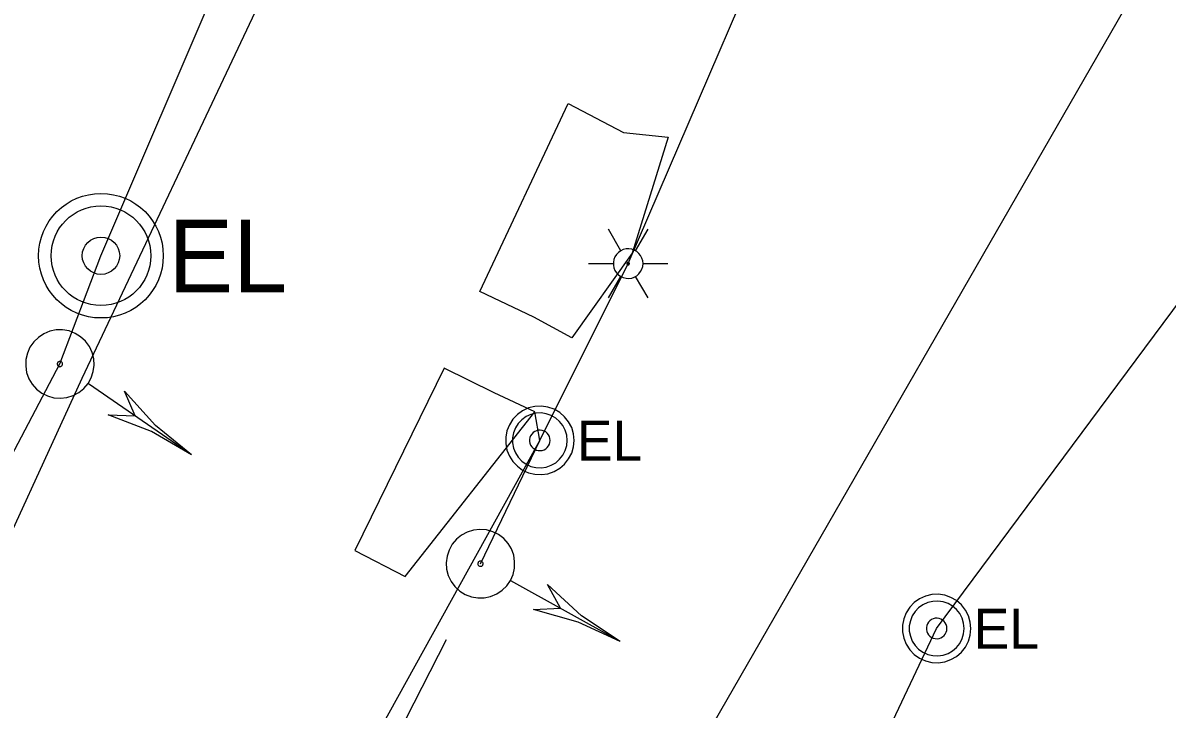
# Model space of a CAD drawing. Extents: x 596028 to 606371, y 330010 to 403088.
# Drawn here: x 604782.6 to 604892.8, y 331025.8 to 331091.9 of the extents above; entities that cross this region are included whole.
import ezdxf

# ---------------------------------------------------------------- set-up
doc = ezdxf.new("R2010")
doc.units = 0
for name, color, linetype in [('E_LTG', 7, 'Continuous'), ('E_SIG', 7, 'Continuous'), ('E_UTL_E', 7, 'Continuous'), ('E_UTL_E_UG', 7, 'Continuous'), ('E_UTL_G_UG', 7, 'Continuous'), ('E_UTL_Loop_UG', 7, 'Continuous'), ('E_UTL_W_UG', 7, 'Continuous')]:
    doc.layers.add(name, color=color, linetype=linetype)

msp = doc.modelspace()

# ---------------------------------------------------------------- linework, layer by layer
at = {"layer": 'E_LTG'}
for points in [[(604840.16, 331069.93), (604838.97, 331071.99)], [(604841.58, 331069.93), (604842.78, 331071.99)], [(604842.3, 331068.69), (604842.27, 331068.96), (604842.2, 331069.22), (604842.07, 331069.46), (604841.9, 331069.67), (604841.7, 331069.85), (604841.46, 331069.99), (604841.21, 331070.08), (604840.94, 331070.12), (604840.67, 331070.1), (604840.4, 331070.04), (604840.16, 331069.93), (604839.93, 331069.77), (604839.75, 331069.57), (604839.6, 331069.34), (604839.5, 331069.09), (604839.45, 331068.82), (604839.45, 331068.55), (604839.5, 331068.29), (604839.6, 331068.03), (604839.75, 331067.8), (604839.93, 331067.61), (604840.16, 331067.45), (604840.4, 331067.34), (604840.67, 331067.27), (604840.94, 331067.26), (604841.21, 331067.3), (604841.46, 331067.39), (604841.7, 331067.52), (604841.9, 331067.7), (604842.07, 331067.92), (604842.2, 331068.16), (604842.27, 331068.42), (604842.3, 331068.69)], [(604842.3, 331068.69), (604842.27, 331068.96), (604842.2, 331069.22), (604842.07, 331069.46), (604841.9, 331069.67), (604841.7, 331069.85), (604841.46, 331069.99), (604841.21, 331070.08), (604840.94, 331070.12), (604840.67, 331070.1), (604840.4, 331070.04), (604840.16, 331069.93), (604839.93, 331069.77), (604839.75, 331069.57), (604839.6, 331069.34), (604839.5, 331069.09), (604839.45, 331068.82), (604839.45, 331068.55), (604839.5, 331068.29), (604839.6, 331068.03), (604839.75, 331067.8), (604839.93, 331067.61), (604840.16, 331067.45), (604840.4, 331067.34), (604840.67, 331067.27), (604840.94, 331067.26), (604841.21, 331067.3), (604841.46, 331067.39), (604841.7, 331067.52), (604841.9, 331067.7), (604842.07, 331067.92), (604842.2, 331068.16), (604842.27, 331068.42), (604842.3, 331068.69)], [(604842.3, 331068.69), (604842.27, 331068.96), (604842.2, 331069.22), (604842.07, 331069.46), (604841.9, 331069.67), (604841.7, 331069.85), (604841.46, 331069.99), (604841.21, 331070.08), (604840.94, 331070.12), (604840.67, 331070.1), (604840.4, 331070.04), (604840.16, 331069.93), (604839.93, 331069.77), (604839.75, 331069.57), (604839.6, 331069.34), (604839.5, 331069.09), (604839.45, 331068.82), (604839.45, 331068.55), (604839.5, 331068.29), (604839.6, 331068.03), (604839.75, 331067.8), (604839.93, 331067.61), (604840.16, 331067.45), (604840.4, 331067.34), (604840.67, 331067.27), (604840.94, 331067.26), (604841.21, 331067.3), (604841.46, 331067.39), (604841.7, 331067.52), (604841.9, 331067.7), (604842.07, 331067.92), (604842.2, 331068.16), (604842.27, 331068.42), (604842.3, 331068.69)], [(604840.99, 331068.69), (604840.99, 331068.71), (604840.98, 331068.73), (604840.97, 331068.75), (604840.96, 331068.77), (604840.94, 331068.78), (604840.92, 331068.8), (604840.9, 331068.8), (604840.88, 331068.81), (604840.85, 331068.81), (604840.83, 331068.8), (604840.81, 331068.79), (604840.79, 331068.78), (604840.78, 331068.76), (604840.76, 331068.74), (604840.76, 331068.72), (604840.75, 331068.7), (604840.75, 331068.68), (604840.76, 331068.65), (604840.76, 331068.63), (604840.78, 331068.61), (604840.79, 331068.6), (604840.81, 331068.58), (604840.83, 331068.58), (604840.85, 331068.57), (604840.88, 331068.57), (604840.9, 331068.57), (604840.92, 331068.58), (604840.94, 331068.59), (604840.96, 331068.61), (604840.97, 331068.62), (604840.98, 331068.64), (604840.99, 331068.67), (604840.99, 331068.69)], [(604837.06, 331068.69), (604839.44, 331068.69)], [(604842.3, 331068.69), (604844.68, 331068.69)], [(604838.97, 331065.39), (604840.16, 331067.45)], [(604842.78, 331065.39), (604841.58, 331067.45)]]:
    msp.add_lwpolyline(points, dxfattribs=at)
at = {"layer": 'E_SIG'}
for points in [[(604788.87, 331057.14), (604789.17, 331057.69), (604789.37, 331058.28), (604789.45, 331058.91), (604789.41, 331059.53), (604789.25, 331060.14), (604788.99, 331060.71), (604788.61, 331061.21), (604788.15, 331061.64), (604787.62, 331061.97), (604787.04, 331062.2), (604786.42, 331062.31), (604785.79, 331062.3), (604785.18, 331062.17), (604784.6, 331061.93), (604784.08, 331061.58), (604783.63, 331061.14), (604783.27, 331060.63), (604783.02, 331060.05), (604782.88, 331059.44), (604782.86, 331058.81), (604782.95, 331058.19), (604783.17, 331057.6), (604783.49, 331057.07), (604783.91, 331056.6), (604784.41, 331056.22), (604784.97, 331055.94), (604785.57, 331055.77), (604786.2, 331055.72), (604786.82, 331055.79), (604787.42, 331055.97), (604787.97, 331056.27), (604788.46, 331056.66), (604788.87, 331057.14)], [(604786.36, 331058.87), (604786.38, 331058.92), (604786.4, 331058.96), (604786.4, 331059.01), (604786.4, 331059.06), (604786.39, 331059.1), (604786.37, 331059.15), (604786.34, 331059.18), (604786.3, 331059.22), (604786.26, 331059.24), (604786.22, 331059.26), (604786.17, 331059.27), (604786.12, 331059.27), (604786.08, 331059.26), (604786.03, 331059.24), (604785.99, 331059.21), (604785.96, 331059.18), (604785.93, 331059.14), (604785.91, 331059.1), (604785.9, 331059.05), (604785.9, 331059), (604785.91, 331058.95), (604785.92, 331058.91), (604785.95, 331058.87), (604785.98, 331058.83), (604786.02, 331058.8), (604786.06, 331058.78), (604786.11, 331058.77), (604786.15, 331058.76), (604786.2, 331058.77), (604786.25, 331058.78), (604786.29, 331058.81), (604786.33, 331058.84), (604786.36, 331058.87)], [(604798.82, 331050.26), (604788.91, 331057.11)], [(604793.39, 331054.01), (604792.36, 331056.4)], [(604798.82, 331050.26), (604795.35, 331053.08), (604792.36, 331056.39)], [(604798.82, 331050.26), (604794.96, 331052.51), (604790.8, 331054.13)], [(604790.8, 331054.13), (604793.39, 331054.01)], [(604829.53, 331038.17), (604829.79, 331038.75), (604829.92, 331039.36), (604829.94, 331039.99), (604829.85, 331040.61), (604829.63, 331041.2), (604829.31, 331041.73), (604828.89, 331042.2), (604828.39, 331042.58), (604827.83, 331042.86), (604827.22, 331043.03), (604826.6, 331043.08), (604825.97, 331043.01), (604825.38, 331042.82), (604824.82, 331042.52), (604824.34, 331042.13), (604823.93, 331041.65), (604823.63, 331041.1), (604823.43, 331040.5), (604823.35, 331039.88), (604823.39, 331039.26), (604823.55, 331038.65), (604823.82, 331038.08), (604824.19, 331037.58), (604824.65, 331037.15), (604825.19, 331036.82), (604825.77, 331036.6), (604826.39, 331036.49), (604827.02, 331036.5), (604827.63, 331036.63), (604828.21, 331036.87), (604828.73, 331037.22), (604829.18, 331037.66), (604829.53, 331038.17)], [(604826.87, 331039.65), (604826.89, 331039.7), (604826.9, 331039.75), (604826.9, 331039.79), (604826.9, 331039.84), (604826.88, 331039.89), (604826.85, 331039.93), (604826.82, 331039.96), (604826.78, 331039.99), (604826.74, 331040.01), (604826.69, 331040.03), (604826.65, 331040.03), (604826.6, 331040.02), (604826.55, 331040.01), (604826.51, 331039.99), (604826.47, 331039.96), (604826.44, 331039.92), (604826.42, 331039.88), (604826.4, 331039.83), (604826.4, 331039.79), (604826.4, 331039.74), (604826.41, 331039.69), (604826.43, 331039.65), (604826.46, 331039.61), (604826.5, 331039.58), (604826.54, 331039.55), (604826.58, 331039.53), (604826.63, 331039.53), (604826.68, 331039.53), (604826.73, 331039.54), (604826.77, 331039.55), (604826.81, 331039.58), (604826.84, 331039.61), (604826.87, 331039.65)], [(604840.11, 331032.29), (604829.58, 331038.14)], [(604840.11, 331032.29), (604836.38, 331034.76), (604833.09, 331037.77)], [(604834.34, 331035.5), (604833.09, 331037.77)], [(604831.75, 331035.37), (604834.34, 331035.5)], [(604840.11, 331032.29), (604836.05, 331034.15), (604831.75, 331035.37)]]:
    msp.add_lwpolyline(points, dxfattribs=at)
at = {"layer": 'E_UTL_E'}
for points in [[(604835.66, 331051.66), (604835.6, 331052.28), (604835.43, 331052.89), (604835.14, 331053.44), (604834.75, 331053.94), (604834.28, 331054.35), (604833.73, 331054.66), (604833.14, 331054.87), (604832.52, 331054.96), (604831.89, 331054.93), (604831.28, 331054.78), (604830.71, 331054.52), (604830.2, 331054.15), (604829.77, 331053.7), (604829.43, 331053.17), (604829.2, 331052.59), (604829.08, 331051.97), (604829.08, 331051.35), (604829.2, 331050.73), (604829.43, 331050.15), (604829.77, 331049.62), (604830.2, 331049.17), (604830.71, 331048.8), (604831.28, 331048.54), (604831.89, 331048.39), (604832.52, 331048.36), (604833.14, 331048.45), (604833.73, 331048.66), (604834.28, 331048.97), (604834.75, 331049.38), (604835.14, 331049.87), (604835.43, 331050.43), (604835.6, 331051.03), (604835.66, 331051.66)], [(604835.66, 331051.66), (604835.6, 331052.28), (604835.43, 331052.89), (604835.14, 331053.44), (604834.75, 331053.94), (604834.28, 331054.35), (604833.73, 331054.66), (604833.14, 331054.87), (604832.52, 331054.96), (604831.89, 331054.93), (604831.28, 331054.78), (604830.71, 331054.52), (604830.2, 331054.15), (604829.77, 331053.7), (604829.43, 331053.17), (604829.2, 331052.59), (604829.08, 331051.97), (604829.08, 331051.35), (604829.2, 331050.73), (604829.43, 331050.15), (604829.77, 331049.62), (604830.2, 331049.17), (604830.71, 331048.8), (604831.28, 331048.54), (604831.89, 331048.39), (604832.52, 331048.36), (604833.14, 331048.45), (604833.73, 331048.66), (604834.28, 331048.97), (604834.75, 331049.38), (604835.14, 331049.87), (604835.43, 331050.43), (604835.6, 331051.03), (604835.66, 331051.66)], [(604835, 331051.66), (604834.95, 331052.16), (604834.81, 331052.64), (604834.58, 331053.09), (604834.27, 331053.48), (604833.89, 331053.81), (604833.46, 331054.06), (604832.98, 331054.22), (604832.49, 331054.3), (604831.99, 331054.27), (604831.5, 331054.15), (604831.04, 331053.95), (604830.63, 331053.65), (604830.29, 331053.29), (604830.02, 331052.87), (604829.83, 331052.4), (604829.73, 331051.91), (604829.73, 331051.41), (604829.83, 331050.92), (604830.02, 331050.45), (604830.29, 331050.03), (604830.63, 331049.66), (604831.04, 331049.37), (604831.5, 331049.16), (604831.99, 331049.05), (604832.49, 331049.02), (604832.98, 331049.09), (604833.46, 331049.26), (604833.89, 331049.51), (604834.27, 331049.84), (604834.58, 331050.23), (604834.81, 331050.68), (604834.95, 331051.16), (604835, 331051.66)], [(604835, 331051.66), (604834.95, 331052.16), (604834.81, 331052.64), (604834.58, 331053.09), (604834.27, 331053.48), (604833.89, 331053.81), (604833.46, 331054.06), (604832.98, 331054.22), (604832.49, 331054.3), (604831.99, 331054.27), (604831.5, 331054.15), (604831.04, 331053.95), (604830.63, 331053.65), (604830.29, 331053.29), (604830.02, 331052.87), (604829.83, 331052.4), (604829.73, 331051.91), (604829.73, 331051.41), (604829.83, 331050.92), (604830.02, 331050.45), (604830.29, 331050.03), (604830.63, 331049.66), (604831.04, 331049.37), (604831.5, 331049.16), (604831.99, 331049.05), (604832.49, 331049.02), (604832.98, 331049.09), (604833.46, 331049.26), (604833.89, 331049.51), (604834.27, 331049.84), (604834.58, 331050.23), (604834.81, 331050.68), (604834.95, 331051.16), (604835, 331051.66)], [(604833.35, 331051.66), (604833.33, 331051.85), (604833.28, 331052.03), (604833.19, 331052.19), (604833.08, 331052.34), (604832.94, 331052.47), (604832.77, 331052.56), (604832.6, 331052.62), (604832.41, 331052.65), (604832.22, 331052.64), (604832.04, 331052.59), (604831.87, 331052.52), (604831.71, 331052.41), (604831.58, 331052.27), (604831.48, 331052.11), (604831.41, 331051.94), (604831.38, 331051.75), (604831.38, 331051.56), (604831.41, 331051.38), (604831.48, 331051.21), (604831.58, 331051.05), (604831.71, 331050.91), (604831.87, 331050.8), (604832.04, 331050.72), (604832.22, 331050.68), (604832.41, 331050.67), (604832.6, 331050.7), (604832.77, 331050.76), (604832.94, 331050.85), (604833.08, 331050.98), (604833.19, 331051.12), (604833.28, 331051.29), (604833.33, 331051.47), (604833.35, 331051.66)], [(604833.35, 331051.66), (604833.33, 331051.85), (604833.28, 331052.03), (604833.19, 331052.19), (604833.08, 331052.34), (604832.94, 331052.47), (604832.77, 331052.56), (604832.6, 331052.62), (604832.41, 331052.65), (604832.22, 331052.64), (604832.04, 331052.59), (604831.87, 331052.52), (604831.71, 331052.41), (604831.58, 331052.27), (604831.48, 331052.11), (604831.41, 331051.94), (604831.38, 331051.75), (604831.38, 331051.56), (604831.41, 331051.38), (604831.48, 331051.21), (604831.58, 331051.05), (604831.71, 331050.91), (604831.87, 331050.8), (604832.04, 331050.72), (604832.22, 331050.68), (604832.41, 331050.67), (604832.6, 331050.7), (604832.77, 331050.76), (604832.94, 331050.85), (604833.08, 331050.98), (604833.19, 331051.12), (604833.28, 331051.29), (604833.33, 331051.47), (604833.35, 331051.66)], [(604873.87, 331033.54), (604873.81, 331034.16), (604873.64, 331034.77), (604873.35, 331035.32), (604872.96, 331035.82), (604872.49, 331036.23), (604871.94, 331036.54), (604871.35, 331036.75), (604870.73, 331036.84), (604870.1, 331036.81), (604869.49, 331036.66), (604868.92, 331036.4), (604868.41, 331036.03), (604867.98, 331035.58), (604867.64, 331035.05), (604867.41, 331034.47), (604867.29, 331033.85), (604867.29, 331033.23), (604867.41, 331032.61), (604867.64, 331032.03), (604867.98, 331031.5), (604868.41, 331031.05), (604868.92, 331030.68), (604869.49, 331030.42), (604870.1, 331030.27), (604870.73, 331030.24), (604871.35, 331030.33), (604871.94, 331030.54), (604872.49, 331030.85), (604872.96, 331031.26), (604873.35, 331031.75), (604873.64, 331032.31), (604873.81, 331032.91), (604873.87, 331033.54)], [(604873.87, 331033.54), (604873.81, 331034.16), (604873.64, 331034.77), (604873.35, 331035.32), (604872.96, 331035.82), (604872.49, 331036.23), (604871.94, 331036.54), (604871.35, 331036.75), (604870.73, 331036.84), (604870.1, 331036.81), (604869.49, 331036.66), (604868.92, 331036.4), (604868.41, 331036.03), (604867.98, 331035.58), (604867.64, 331035.05), (604867.41, 331034.47), (604867.29, 331033.85), (604867.29, 331033.23), (604867.41, 331032.61), (604867.64, 331032.03), (604867.98, 331031.5), (604868.41, 331031.05), (604868.92, 331030.68), (604869.49, 331030.42), (604870.1, 331030.27), (604870.73, 331030.24), (604871.35, 331030.33), (604871.94, 331030.54), (604872.49, 331030.85), (604872.96, 331031.26), (604873.35, 331031.75), (604873.64, 331032.31), (604873.81, 331032.91), (604873.87, 331033.54)], [(604873.21, 331033.54), (604873.16, 331034.04), (604873.02, 331034.52), (604872.79, 331034.97), (604872.48, 331035.36), (604872.1, 331035.69), (604871.67, 331035.94), (604871.19, 331036.1), (604870.7, 331036.18), (604870.2, 331036.15), (604869.71, 331036.03), (604869.25, 331035.83), (604868.84, 331035.53), (604868.5, 331035.17), (604868.23, 331034.75), (604868.04, 331034.28), (604867.94, 331033.79), (604867.94, 331033.29), (604868.04, 331032.8), (604868.23, 331032.33), (604868.5, 331031.91), (604868.84, 331031.54), (604869.25, 331031.25), (604869.71, 331031.04), (604870.2, 331030.93), (604870.7, 331030.9), (604871.19, 331030.97), (604871.67, 331031.14), (604872.1, 331031.39), (604872.48, 331031.72), (604872.79, 331032.11), (604873.02, 331032.56), (604873.16, 331033.04), (604873.21, 331033.54)], [(604873.21, 331033.54), (604873.16, 331034.04), (604873.02, 331034.52), (604872.79, 331034.97), (604872.48, 331035.36), (604872.1, 331035.69), (604871.67, 331035.94), (604871.19, 331036.1), (604870.7, 331036.18), (604870.2, 331036.15), (604869.71, 331036.03), (604869.25, 331035.83), (604868.84, 331035.53), (604868.5, 331035.17), (604868.23, 331034.75), (604868.04, 331034.28), (604867.94, 331033.79), (604867.94, 331033.29), (604868.04, 331032.8), (604868.23, 331032.33), (604868.5, 331031.91), (604868.84, 331031.54), (604869.25, 331031.25), (604869.71, 331031.04), (604870.2, 331030.93), (604870.7, 331030.9), (604871.19, 331030.97), (604871.67, 331031.14), (604872.1, 331031.39), (604872.48, 331031.72), (604872.79, 331032.11), (604873.02, 331032.56), (604873.16, 331033.04), (604873.21, 331033.54)], [(604871.56, 331033.54), (604871.54, 331033.73), (604871.49, 331033.91), (604871.4, 331034.07), (604871.29, 331034.22), (604871.15, 331034.35), (604870.98, 331034.44), (604870.81, 331034.5), (604870.62, 331034.53), (604870.43, 331034.52), (604870.25, 331034.47), (604870.08, 331034.4), (604869.92, 331034.29), (604869.79, 331034.15), (604869.69, 331033.99), (604869.62, 331033.82), (604869.59, 331033.63), (604869.59, 331033.44), (604869.62, 331033.26), (604869.69, 331033.09), (604869.79, 331032.93), (604869.92, 331032.79), (604870.08, 331032.68), (604870.25, 331032.6), (604870.43, 331032.56), (604870.62, 331032.55), (604870.81, 331032.58), (604870.98, 331032.64), (604871.15, 331032.73), (604871.29, 331032.86), (604871.4, 331033), (604871.49, 331033.17), (604871.54, 331033.35), (604871.56, 331033.54)], [(604871.56, 331033.54), (604871.54, 331033.73), (604871.49, 331033.91), (604871.4, 331034.07), (604871.29, 331034.22), (604871.15, 331034.35), (604870.98, 331034.44), (604870.81, 331034.5), (604870.62, 331034.53), (604870.43, 331034.52), (604870.25, 331034.47), (604870.08, 331034.4), (604869.92, 331034.29), (604869.79, 331034.15), (604869.69, 331033.99), (604869.62, 331033.82), (604869.59, 331033.63), (604869.59, 331033.44), (604869.62, 331033.26), (604869.69, 331033.09), (604869.79, 331032.93), (604869.92, 331032.79), (604870.08, 331032.68), (604870.25, 331032.6), (604870.43, 331032.56), (604870.62, 331032.55), (604870.81, 331032.58), (604870.98, 331032.64), (604871.15, 331032.73), (604871.29, 331032.86), (604871.4, 331033), (604871.49, 331033.17), (604871.54, 331033.35), (604871.56, 331033.54)]]:
    msp.add_lwpolyline(points, dxfattribs=at)
for radius in [6, 6, 4.8, 4.8, 1.8, 1.8]:
    msp.add_circle((604790.11, 331069.45), radius, dxfattribs=at)
at = {"layer": 'E_UTL_E_UG'}
for points in [[(604870.57, 331033.54), (605033.08, 331252.35), (605033.08, 331392.8), (605061.51, 331399.86), (605069.48, 331571.07), (605141.68, 331571.07)], [(604826.65, 331039.78), (604832.36, 331051.66), (604840.87, 331068.69), (604891.55, 331186.46), (604898.79, 331199.69), (604899.88, 331201.84), (604900.68, 331206.84), (604943.56, 331338.75), (604983.14, 331477.94)], [(604683.3, 330952.09), (604722.4, 330946.58), (604729.82, 330955.05), (604742.66, 330976.26), (604786.15, 331059.02), (604790.11, 331069.45), (604882.51, 331285.09), (604891.05, 331283.2)], [(604695.73, 330748.29), (604684.95, 330755.93), (604681.24, 330750.97), (604664.85, 330762.93), (604668.47, 330767.86), (604688.35, 330805.65), (604694.41, 330818.48), (604703.37, 330832.03), (604758.06, 330920.64), (604761.47, 330923.51), (604832.36, 331051.66)], [(604799.82, 330903.8), (604803.36, 330910.48), (604806.81, 330916.16), (604807.17, 330917.51), (604812.14, 330921.54), (604814.79, 330925.04), (604818.18, 330929.76), (604824.24, 330938.55), (604847.97, 330975.86), (604850.43, 330981.39), (604851.88, 330993.19), (604856.34, 331003.45), (604870.57, 331033.54)]]:
    msp.add_lwpolyline(points, dxfattribs=at)
at = {"layer": 'E_UTL_G_UG'}
msp.add_lwpolyline([(604718.21, 330825.28), (604738.73, 330857.66), (604733.36, 330874.38), (604732.32, 330894.54), (604729.33, 330913.4), (604725.16, 330938.36), (604752.74, 330988.13), (604778.16, 331035.55), (604788.31, 331057.65), (604805.53, 331094.16), (604828.8, 331144.07), (604848.89, 331191.36), (604869.57, 331244.15), (604888.61, 331295.88), (604900.58, 331325.56), (604922.44, 331394.24)], dxfattribs=at)
at = {"layer": 'E_UTL_Loop_UG'}
for points in [[(604844.72, 331080.86), (604841.27, 331069.71), (604835.45, 331061.55), (604831.79, 331063.54), (604826.59, 331066.01), (604835.1, 331084.12), (604840.43, 331081.32), (604844.72, 331080.86)], [(604832.36, 331051.66), (604831.87, 331054.4), (604827.97, 331056.24), (604823.16, 331058.61), (604814.56, 331041.06), (604819.41, 331038.55), (604831.87, 331054.4)]]:
    msp.add_lwpolyline(points, dxfattribs=at)
at = {"layer": 'E_UTL_W_UG'}
msp.add_line((604787.22, 330962.08), (604823.39, 331032.48), dxfattribs=at)
msp.add_lwpolyline([(604662.85, 330776.78), (604719.99, 330861.17), (604771.51, 330900.13), (604792.62, 330926.22), (604804.59, 330947.13), (605054.68, 331381.7), (605055.13, 331442.45), (605044.65, 331474.36), (605047.01, 331851.63), (605038.36, 332278.66), (605035.8, 332410.28), (605072.23, 332411.32), (605076.98, 332411.12), (605079.88, 332411.16)], dxfattribs=at)

# ---------------------------------------------------------------- texts
at = {"layer": 'E_UTL_E'}
for height, p in [(6.998, (604796.59, 331065.91)), (6.998, (604796.59, 331065.91)), (3.849, (604835.93, 331049.71)), (3.849, (604835.93, 331049.71)), (3.849, (604874.14, 331031.59)), (3.849, (604874.14, 331031.59))]:
    msp.add_text('EL', height=height, dxfattribs=at).set_placement(p)

doc.saveas('drawing.dxf')
